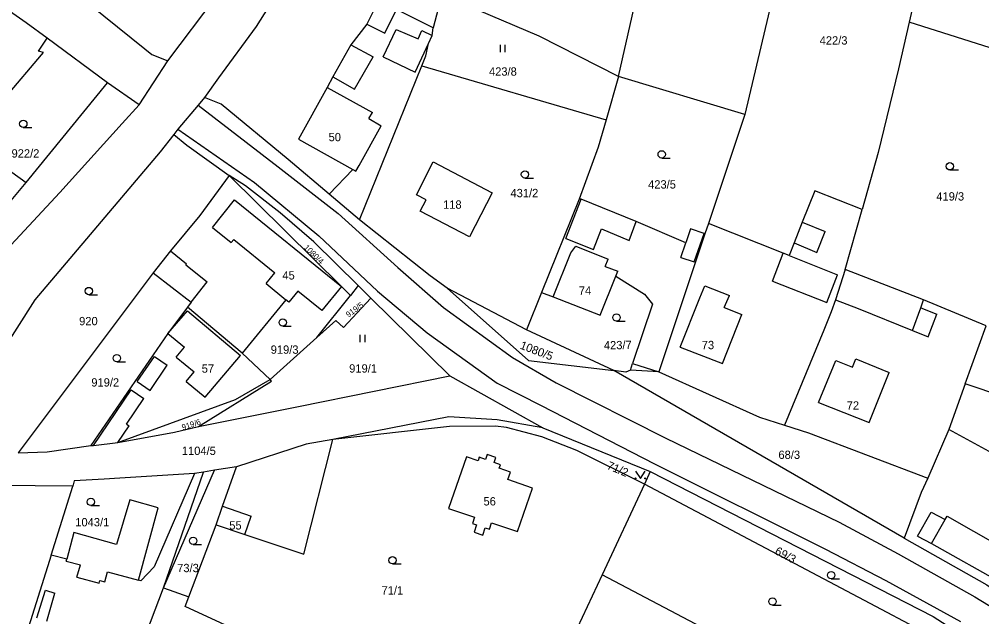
# Model space of a CAD drawing. Extents: x -746176 to -739709, y -1128407 to -1124482.
# Drawn here: x -742573.8 to -742377, y -1125982.8 to -1125860.6 of the extents above; entities that cross this region are included whole.
import ezdxf

# ---------------------------------------------------------------- set-up
doc = ezdxf.new("R2010")
doc.units = 0
for name, color, linetype in [('Hranice parcel', 7, 'Continuous'), ('Parcelní čísla', 7, 'Continuous'), ('Vnitřní kresba', 7, 'Continuous'), ('Značky kultur', 7, 'Continuous')]:
    doc.layers.add(name, color=color, linetype=linetype)

msp = doc.modelspace()

# ---------------------------------------------------------------- linework, layer by layer
at = {"layer": 'Hranice parcel'}
for p, q in [((-742411.59, -1125821.74), (-742425.41, -1125880.06)), ((-742386.83, -1125839.6), (-742391.8, -1125861.15)), ((-742487.36, -1125855.55), (-742489.14, -1125862.33)), ((-742361.26, -1125870.87), (-742391.8, -1125861.15)), ((-742555.75, -1125873.58), (-742568.08, -1125864.47)), ((-742549.27, -1125878.06), (-742543.37, -1125869.11)), ((-742504.18, -1125901.64), (-742491.48, -1125870.12)), ((-742491.48, -1125870.12), (-742453.8, -1125881.12)), ((-742451.26, -1125872.3), (-742453.8, -1125881.12)), ((-742425.41, -1125880.06), (-742451.26, -1125872.3)), ((-742572.38, -1125894), (-742555.75, -1125873.58)), ((-742549.27, -1125878.06), (-742555.75, -1125873.58)), ((-742425.41, -1125880.06), (-742432.86, -1125902.34)), ((-742583.94, -1125885.69), (-742572.38, -1125894)), ((-742530.83, -1125892.53), (-742507.9, -1125915.25)), ((-742577.49, -1125900.11), (-742572.38, -1125894)), ((-742504.18, -1125901.64), (-742510.39, -1125896.37)), ((-742459.32, -1125897.41), (-742466.99, -1125916.45)), ((-742404.91, -1125911.78), (-742401.44, -1125899.49)), ((-742432.86, -1125902.34), (-742433.58, -1125904.47)), ((-742433.58, -1125904.47), (-742443.02, -1125932.7)), ((-742546.38, -1125912.47), (-742573.99, -1125949.25)), ((-742506.08, -1125917.05), (-742507.9, -1125915.25)), ((-742504.5, -1125915.04), (-742506.08, -1125917.05)), ((-742470.08, -1125924.13), (-742486.25, -1125915.58)), ((-742466.99, -1125916.45), (-742470.08, -1125924.13)), ((-742512.91, -1125925.68), (-742506.08, -1125917.05)), ((-742501.86, -1125917.64), (-742485.76, -1125933.54)), ((-742528.19, -1125928.89), (-742539.35, -1125919.44)), ((-742452.23, -1125932.44), (-742470.08, -1125924.13)), ((-742380.33, -1125935.12), (-742376.04, -1125923.32)), ((-742522.47, -1125934.25), (-742512.91, -1125925.68)), ((-742522.47, -1125934.25), (-742528.19, -1125928.89)), ((-742485.76, -1125933.54), (-742466.73, -1125944.13)), ((-742392.86, -1125966.72), (-742452.23, -1125932.44)), ((-742380.33, -1125935.12), (-742383.73, -1125944.51)), ((-742354.55, -1125943.93), (-742380.33, -1125935.12)), ((-742466.73, -1125944.13), (-742444.75, -1125953.11)), ((-742383.73, -1125944.51), (-742387.99, -1125954.45)), ((-742360.59, -1125957.08), (-742383.73, -1125944.51)), ((-742544.26, -1125976.88), (-742536.12, -1125953.2)), ((-742536.12, -1125953.2), (-742537.98, -1125953.5)), ((-742444.75, -1125953.11), (-742445.94, -1125955.65)), ((-742445.94, -1125955.65), (-742454.6, -1125974.2)), ((-742562.86, -1125956.05), (-742581.95, -1125955.95)), ((-742567.25, -1125970.2), (-742562.86, -1125956.05)), ((-742539.1, -1125978.71), (-742533.51, -1125963.98)), ((-742567.25, -1125970.2), (-742573.08, -1125988.58)), ((-742454.6, -1125974.2), (-742470.09, -1126007.17)), ((-742544.26, -1125976.88), (-742539.1, -1125978.71))]:
    msp.add_line(p, q, dxfattribs=at)
for points in [[(-742451.26, -1125872.3), (-742423.93, -1125751.58), (-742396.6, -1125630.87)], [(-742469.87, -1125754.46), (-742479.12, -1125772.95), (-742512.08, -1125840.96), (-742525.31, -1125862.03), (-742533.06, -1125872.56), (-742535.93, -1125876.56)], [(-742543.37, -1125869.11), (-742533.49, -1125855.94), (-742526.37, -1125842.12)], [(-742568.08, -1125864.47), (-742572.39, -1125861.31), (-742586.54, -1125851.33), (-742591, -1125848.62), (-742591.99, -1125848.03)], [(-742567.01, -1125851.37), (-742556.52, -1125859.9), (-742548.11, -1125866.6), (-742546.65, -1125867.77), (-742543.37, -1125869.11)], [(-742489.14, -1125862.33), (-742496.61, -1125858.56), (-742500.28, -1125856.71), (-742502.73, -1125861.57), (-742505.97, -1125865.78), (-742509.67, -1125872.35), (-742510.8, -1125874.53), (-742516.67, -1125885.09), (-742505.56, -1125891.34), (-742510.39, -1125896.37)], [(-742451.26, -1125872.3), (-742467.46, -1125864.05), (-742487.36, -1125855.55)], [(-742391.8, -1125861.15), (-742394.01, -1125870.7), (-742398.15, -1125887.84), (-742401.44, -1125899.49)], [(-742491.48, -1125870.12), (-742490.64, -1125868.04), (-742490.08, -1125865.53), (-742489.36, -1125863.92), (-742489.14, -1125862.33)], [(-742583.94, -1125885.69), (-742576.4, -1125876.29), (-742569.23, -1125867.87), (-742568.85, -1125867.39), (-742569.85, -1125867.14), (-742568.08, -1125864.47)], [(-742535.93, -1125876.56), (-742537.22, -1125878.12), (-742541.33, -1125883.08), (-742542.15, -1125884.13)], [(-742510.39, -1125896.37), (-742518.81, -1125889.24), (-742532.53, -1125877.94), (-742535.93, -1125876.56)], [(-742622.9, -1125956.15), (-742614.33, -1125945.77), (-742586.39, -1125918.45), (-742565.5, -1125896.03), (-742552.77, -1125881.87), (-742549.27, -1125878.06)], [(-742453.8, -1125881.12), (-742455.42, -1125886.74), (-742459.32, -1125897.41)], [(-742542.15, -1125884.13), (-742544.97, -1125887.72), (-742570.58, -1125918), (-742581.73, -1125935.37), (-742588.9, -1125948.74)], [(-742542.15, -1125884.13), (-742539.55, -1125886.34), (-742530.83, -1125892.53)], [(-742489.14, -1125889.75), (-742477.05, -1125896.1), (-742481.69, -1125905.09), (-742491.81, -1125899.8), (-742490.57, -1125897.54), (-742492.53, -1125896.46), (-742489.14, -1125889.75)], [(-742530.83, -1125892.53), (-742536.83, -1125900.7), (-742542.88, -1125907.93), (-742546.38, -1125912.47)], [(-742504.5, -1125915.04), (-742513.55, -1125906.11), (-742520.44, -1125900.17), (-742527.49, -1125894.67), (-742530.83, -1125892.53)], [(-742401.44, -1125899.49), (-742411.12, -1125895.65), (-742413.66, -1125902.11), (-742415.31, -1125906.31), (-742416.34, -1125908.93), (-742417.54, -1125908.45), (-742432.86, -1125902.34)], [(-742433.58, -1125904.47), (-742433.71, -1125904.43), (-742436.54, -1125903.47), (-742437.49, -1125906.29), (-742447.62, -1125901.95), (-742458.86, -1125897.36), (-742459.32, -1125897.41)], [(-742486.25, -1125915.58), (-742489.77, -1125913.07), (-742504.18, -1125901.64)], [(-742546.38, -1125912.47), (-742538.61, -1125918.44), (-742539.35, -1125919.44)], [(-742404.91, -1125911.78), (-742406.86, -1125917.94), (-742407.78, -1125920.45), (-742409.26, -1125924.16), (-742417.31, -1125943.6)], [(-742376.04, -1125923.32), (-742388.87, -1125917.99), (-742404.91, -1125911.78)], [(-742466.99, -1125916.45), (-742464.6, -1125917.38), (-742455, -1125921.11), (-742451.78, -1125913.15), (-742445.93, -1125916.84), (-742444.31, -1125918.83), (-742448.37, -1125931), (-742443.02, -1125932.7)], [(-742507.9, -1125915.25), (-742511.91, -1125920.18), (-742516.83, -1125916.2), (-742518.65, -1125918.45), (-742519.27, -1125917.94), (-742528.19, -1125928.89)], [(-742501.86, -1125917.64), (-742502.85, -1125916.66), (-742504.5, -1125915.04)], [(-742486.25, -1125915.58), (-742469.64, -1125930.37), (-742452.23, -1125932.44)], [(-742512.91, -1125925.68), (-742509.05, -1125922.22), (-742507.49, -1125923.6), (-742501.86, -1125917.64)], [(-742539.35, -1125919.44), (-742543.4, -1125924.86), (-742559.16, -1125947.76)], [(-742537.1, -1125943.85), (-742516.7, -1125939.77), (-742485.76, -1125933.54)], [(-742443.02, -1125932.7), (-742448.82, -1125932.36), (-742449.74, -1125932.78), (-742452.23, -1125932.44)], [(-742443.02, -1125932.7), (-742422.4, -1125941.96), (-742417.31, -1125943.6)], [(-742553.65, -1125947.14), (-742529.57, -1125938.33), (-742522.47, -1125934.25)], [(-742537.1, -1125943.85), (-742522.23, -1125934.58), (-742522.47, -1125934.25)], [(-742466.73, -1125944.13), (-742476.04, -1125942.52), (-742485.91, -1125941.93), (-742509.68, -1125946.54)], [(-742553.65, -1125947.14), (-742542.05, -1125945.01), (-742537.1, -1125943.85)], [(-742445.94, -1125955.65), (-742459.75, -1125948.8), (-742466.89, -1125946.02), (-742474.13, -1125944.08), (-742476.37, -1125943.84), (-742485.83, -1125943.85), (-742509.68, -1125946.54)], [(-742417.31, -1125943.6), (-742412.38, -1125945.19), (-742387.99, -1125954.45)], [(-742573.99, -1125949.25), (-742568.11, -1125949.08), (-742559.16, -1125947.76)], [(-742559.16, -1125947.76), (-742558.57, -1125947.74), (-742553.65, -1125947.14)], [(-742533.51, -1125963.98), (-742527.67, -1125965.96), (-742515.61, -1125969.96), (-742509.68, -1125946.54)], [(-742509.68, -1125946.54), (-742515.14, -1125947.5), (-742529.35, -1125952.1)], [(-742480.68, -1125962.42), (-742481.12, -1125963.73), (-742480.27, -1125964.02), (-742480.78, -1125965.52), (-742479, -1125966.12), (-742478.49, -1125964.62), (-742477.64, -1125964.9), (-742477.2, -1125963.59), (-742471.89, -1125965.38), (-742468.82, -1125956.52), (-742473.86, -1125954.74), (-742473.34, -1125953.24), (-742475.63, -1125952.43), (-742475.36, -1125951.69), (-742476.67, -1125951.22), (-742476.32, -1125950.24), (-742478.09, -1125949.62), (-742478.44, -1125950.6), (-742479.71, -1125950.15), (-742479.97, -1125950.9), (-742482.31, -1125950.08), (-742485.99, -1125960.63), (-742480.68, -1125962.42)], [(-742537.98, -1125953.5), (-742546.21, -1125972.61), (-742548.93, -1125975.45), (-742549.4, -1125975.3), (-742545.39, -1125960.48), (-742551.14, -1125958.9), (-742553.87, -1125967.99), (-742562.62, -1125965.54), (-742564.09, -1125970.98), (-742567.25, -1125970.2)], [(-742537.98, -1125953.5), (-742553.22, -1125954.47), (-742556.43, -1125954.63), (-742562.53, -1125955), (-742562.86, -1125956.05)], [(-742529.35, -1125952.1), (-742533.86, -1125952.83), (-742536.12, -1125953.2)], [(-742533.51, -1125963.98), (-742532.24, -1125960.14), (-742529.35, -1125952.1)], [(-742444.75, -1125953.11), (-742386.93, -1125982.77), (-742380.97, -1125986.53)], [(-742382.69, -1125989.14), (-742398.6, -1125980.67), (-742445.94, -1125955.65)], [(-742387.99, -1125954.45), (-742389.36, -1125957.36), (-742392.86, -1125966.72)], [(-742392.86, -1125966.72), (-742375.94, -1125976.23), (-742374.7, -1125977.14), (-742365.43, -1125982.55)], [(-742399.65, -1126003.37), (-742408.8, -1125998.36), (-742454.6, -1125974.2)], [(-742550.22, -1125993.2), (-742548.63, -1125988.42), (-742544.26, -1125976.88)], [(-742525.42, -1125987.39), (-742539.86, -1125980.7), (-742539.1, -1125978.71)]]:
    msp.add_lwpolyline(points, dxfattribs=at)
at = {"layer": 'Vnitřní kresba'}
for p, q in [((-742499.06, -1125863.42), (-742496.61, -1125858.56)), ((-742502.73, -1125861.57), (-742499.06, -1125863.42)), ((-742499.35, -1125868.29), (-742496.68, -1125862.69)), ((-742496.68, -1125862.69), (-742492.2, -1125864.62)), ((-742492.2, -1125864.62), (-742491.45, -1125862.87)), ((-742491.45, -1125862.87), (-742489.36, -1125863.92)), ((-742505.97, -1125865.78), (-742501.44, -1125868.3)), ((-742492.84, -1125871.4), (-742490.08, -1125865.53)), ((-742505.24, -1125874.9), (-742501.44, -1125868.3)), ((-742499.35, -1125868.29), (-742492.84, -1125871.4)), ((-742509.67, -1125872.35), (-742505.24, -1125874.9)), ((-742510.8, -1125874.53), (-742501.54, -1125879.62)), ((-742537.22, -1125878.12), (-742520.87, -1125890.79)), ((-742502.29, -1125880.85), (-742501.54, -1125879.62)), ((-742502.29, -1125880.85), (-742499.81, -1125882.36)), ((-742504.3, -1125890.51), (-742499.81, -1125882.36)), ((-742541.33, -1125883.08), (-742525.71, -1125893.94)), ((-742520.87, -1125890.79), (-742508.59, -1125900.34)), ((-742504.95, -1125891.68), (-742504.3, -1125890.51)), ((-742505.56, -1125891.34), (-742504.95, -1125891.68)), ((-742525.71, -1125893.94), (-742512.5, -1125904.89)), ((-742534.26, -1125903.18), (-742529.78, -1125897.51)), ((-742529.78, -1125897.51), (-742507.9, -1125915.25)), ((-742462.03, -1125905.4), (-742458.86, -1125897.36)), ((-742508.59, -1125900.34), (-742496.39, -1125911.34)), ((-742449.09, -1125905.82), (-742447.62, -1125901.95)), ((-742413.66, -1125902.11), (-742408.97, -1125903.96)), ((-742534.26, -1125903.18), (-742530.45, -1125906.26)), ((-742456.37, -1125907.69), (-742454.71, -1125903.47)), ((-742454.71, -1125903.47), (-742449.09, -1125905.82)), ((-742435.76, -1125910.23), (-742433.71, -1125904.43)), ((-742410.72, -1125908.26), (-742408.97, -1125903.96)), ((-742530.45, -1125906.26), (-742529.92, -1125905.6)), ((-742529.92, -1125905.6), (-742521.49, -1125912.43)), ((-742512.5, -1125904.89), (-742500.56, -1125916.22)), ((-742462.03, -1125905.4), (-742456.37, -1125907.69)), ((-742438.5, -1125909.28), (-742437.49, -1125906.29)), ((-742415.31, -1125906.31), (-742410.72, -1125908.26)), ((-742542.88, -1125907.93), (-742539.57, -1125910.59)), ((-742464.6, -1125917.38), (-742461.01, -1125908.34)), ((-742461.01, -1125908.34), (-742459.99, -1125907.02)), ((-742459.99, -1125907.02), (-742453.33, -1125909.63)), ((-742419.77, -1125914.17), (-742417.54, -1125908.45)), ((-742539.74, -1125910.8), (-742539.57, -1125910.59)), ((-742453.97, -1125911.14), (-742453.33, -1125909.63)), ((-742438.5, -1125909.28), (-742435.76, -1125910.23)), ((-742416.34, -1125908.93), (-742406.43, -1125912.88)), ((-742539.74, -1125910.8), (-742535.33, -1125914.3)), ((-742523.28, -1125914.65), (-742521.49, -1125912.43)), ((-742496.39, -1125911.34), (-742487.01, -1125919.55)), ((-742453.97, -1125911.14), (-742451.37, -1125912.13)), ((-742451.78, -1125913.15), (-742451.37, -1125912.13)), ((-742538.61, -1125918.44), (-742535.33, -1125914.3)), ((-742419.77, -1125914.17), (-742408.63, -1125918.53)), ((-742408.63, -1125918.53), (-742406.43, -1125912.88)), ((-742523.28, -1125914.65), (-742519.27, -1125917.94)), ((-742500.56, -1125916.22), (-742490.34, -1125924.69)), ((-742434.59, -1125917.55), (-742433.61, -1125915.09)), ((-742433.61, -1125915.09), (-742428.57, -1125917.11)), ((-742438.62, -1125927.64), (-742434.59, -1125917.55)), ((-742429.64, -1125919.52), (-742428.57, -1125917.11)), ((-742406.86, -1125917.94), (-742402.22, -1125919.77)), ((-742389.45, -1125919.59), (-742388.87, -1125917.99)), ((-742543.4, -1125924.86), (-742539.39, -1125920.19)), ((-742539.39, -1125920.19), (-742528.55, -1125929.36)), ((-742487.01, -1125919.55), (-742472.93, -1125929.77)), ((-742429.64, -1125919.52), (-742426.02, -1125920.95)), ((-742402.22, -1125919.77), (-742391.15, -1125924.26)), ((-742391.15, -1125924.26), (-742389.45, -1125919.59)), ((-742389.45, -1125919.59), (-742386.16, -1125920.91)), ((-742430.01, -1125931), (-742426.02, -1125920.95)), ((-742387.95, -1125925.55), (-742386.16, -1125920.91)), ((-742391.15, -1125924.26), (-742387.95, -1125925.55)), ((-742543.4, -1125924.86), (-742540.01, -1125927.67)), ((-742490.34, -1125924.69), (-742476.09, -1125935.01)), ((-742541.69, -1125929.69), (-742540.01, -1125927.67)), ((-742438.62, -1125927.64), (-742430.01, -1125931)), ((-742549.68, -1125934.66), (-742546.11, -1125929.56)), ((-742546.11, -1125929.56), (-742543.54, -1125931.35)), ((-742541.69, -1125929.69), (-742538.01, -1125932.67)), ((-742535.78, -1125937.86), (-742528.55, -1125929.36)), ((-742472.93, -1125929.77), (-742464.02, -1125934.96)), ((-742403.4, -1125931.74), (-742402.73, -1125930.07)), ((-742402.73, -1125930.07), (-742395.9, -1125932.8)), ((-742547.03, -1125936.52), (-742543.54, -1125931.35)), ((-742448.82, -1125932.36), (-742448.37, -1125931)), ((-742410.34, -1125939), (-742406.83, -1125930.35)), ((-742406.83, -1125930.35), (-742403.4, -1125931.74)), ((-742539.64, -1125934.64), (-742538.01, -1125932.67)), ((-742399.99, -1125943.09), (-742395.9, -1125932.8)), ((-742549.68, -1125934.66), (-742547.03, -1125936.52)), ((-742539.64, -1125934.64), (-742535.78, -1125937.86)), ((-742476.09, -1125935.01), (-742467.07, -1125939.61)), ((-742464.02, -1125934.96), (-742441.6, -1125946.26)), ((-742558.57, -1125947.74), (-742550.88, -1125936.37)), ((-742551.86, -1125943.37), (-742548.32, -1125938.17)), ((-742550.88, -1125936.37), (-742548.32, -1125938.17)), ((-742467.07, -1125939.61), (-742443.89, -1125951.53)), ((-742410.34, -1125939), (-742399.99, -1125943.09)), ((-742553.65, -1125947.14), (-742551.32, -1125943.73)), ((-742551.86, -1125943.37), (-742551.32, -1125943.73)), ((-742441.6, -1125946.26), (-742406.15, -1125963.41)), ((-742443.89, -1125951.53), (-742408.92, -1125968.97)), ((-742544.26, -1125976.88), (-742533.86, -1125952.83)), ((-742532.24, -1125960.14), (-742526.35, -1125962.21)), ((-742390.09, -1125966.29), (-742387.32, -1125961.4)), ((-742387.32, -1125961.4), (-742384.45, -1125962.91)), ((-742527.67, -1125965.96), (-742526.35, -1125962.21)), ((-742406.15, -1125963.41), (-742394.08, -1125969.92)), ((-742387.23, -1125967.82), (-742384.45, -1125962.91)), ((-742384.45, -1125962.91), (-742384.05, -1125962.22)), ((-742384.05, -1125962.22), (-742373.29, -1125968.32)), ((-742390.09, -1125966.29), (-742387.23, -1125967.82)), ((-742408.92, -1125968.97), (-742396.61, -1125975.35)), ((-742387.23, -1125967.82), (-742366.83, -1125979.29)), ((-742564.2, -1125971.41), (-742564.09, -1125970.98)), ((-742564.2, -1125971.41), (-742561.24, -1125972.19)), ((-742394.08, -1125969.92), (-742378.39, -1125978.73)), ((-742562.02, -1125974.66), (-742561.24, -1125972.19)), ((-742562.02, -1125974.66), (-742557.45, -1125975.89)), ((-742557.45, -1125975.89), (-742557.3, -1125975.35)), ((-742557.3, -1125975.35), (-742556.28, -1125975.62)), ((-742556.28, -1125975.62), (-742555.76, -1125973.63)), ((-742555.76, -1125973.63), (-742549.4, -1125975.3)), ((-742396.61, -1125975.35), (-742381.3, -1125983.74)), ((-742570.16, -1125983.03), (-742568.42, -1125977.34)), ((-742568.42, -1125977.34), (-742566.48, -1125977.96)), ((-742568.14, -1125983.67), (-742566.48, -1125977.96)), ((-742378.39, -1125978.73), (-742362.72, -1125988.35))]:
    msp.add_line(p, q, dxfattribs=at)
at = {"layer": 'Značky kultur'}
for p, q in [((-742475.41, -1125867.31), (-742475.41, -1125865.81)), ((-742474.41, -1125867.31), (-742474.41, -1125865.81)), ((-742572.96, -1125882.73), (-742571.21, -1125882.73)), ((-742442.41, -1125888.96), (-742440.66, -1125888.96)), ((-742383.48, -1125891.41), (-742381.73, -1125891.41)), ((-742470.38, -1125893.06), (-742468.63, -1125893.06)), ((-742559.56, -1125916.92), (-742557.81, -1125916.92)), ((-742451.65, -1125922.32), (-742449.9, -1125922.32)), ((-742519.91, -1125923.36), (-742518.16, -1125923.36)), ((-742504.06, -1125926.6), (-742504.06, -1125925.1)), ((-742503.06, -1125926.6), (-742503.06, -1125925.1)), ((-742553.84, -1125930.64), (-742552.09, -1125930.64)), ((-742559.13, -1125960.05), (-742557.38, -1125960.05)), ((-742538.24, -1125968), (-742536.49, -1125968)), ((-742497.45, -1125971.99), (-742495.7, -1125971.99)), ((-742407.77, -1125975.03), (-742406.02, -1125975.03)), ((-742419.74, -1125980.43), (-742417.99, -1125980.43))]:
    msp.add_line(p, q, dxfattribs=at)
msp.add_lwpolyline([(-742447.78, -1125952.99), (-742446.78, -1125954.49), (-742445.78, -1125952.99)], dxfattribs=at)
for centre, radius in [((-742572.96, -1125881.98), 0.75), ((-742442.41, -1125888.21), 0.75), ((-742383.48, -1125890.66), 0.75), ((-742470.38, -1125892.31), 0.75), ((-742559.56, -1125916.17), 0.75), ((-742519.91, -1125922.61), 0.75), ((-742451.65, -1125921.57), 0.75), ((-742553.84, -1125929.89), 0.75), ((-742447.78, -1125954.49), 0.1), ((-742445.78, -1125954.49), 0.1), ((-742559.13, -1125959.3), 0.75), ((-742538.24, -1125967.25), 0.75), ((-742497.45, -1125971.24), 0.75), ((-742407.77, -1125974.28), 0.75), ((-742419.74, -1125979.68), 0.75)]:
    msp.add_circle(centre, radius, dxfattribs=at)

# ---------------------------------------------------------------- texts
at = {"layer": 'Parcelní čísla'}
for s, p in [('422/3', (-742410.11, -1125865.76)), ('423/8', (-742477.73, -1125872.12)), ('50', (-742510.53, -1125885.53)), ('922/2', (-742575.36, -1125888.87)), ('423/5', (-742445.19, -1125895.21)), ('431/2', (-742473.34, -1125896.98)), ('419/3', (-742386.26, -1125897.66)), ('118', (-742487.12, -1125899.34)), ('45', (-742519.98, -1125913.81)), ('74', (-742459.36, -1125916.92)), ('920', (-742561.54, -1125923.17)), ('73', (-742434.22, -1125928.06)), ('919/3', (-742522.37, -1125929)), ('57', (-742536.47, -1125932.87)), ('919/1', (-742506.32, -1125932.85)), ('919/2', (-742559.05, -1125935.71)), ('72', (-742404.58, -1125940.42)), ('1104/5', (-742540.54, -1125949.7)), ('68/3', (-742418.54, -1125950.51)), ('56', (-742478.85, -1125960.03)), ('1043/1', (-742562.33, -1125964.3)), ('55', (-742530.84, -1125964.95)), ('73/3', (-742541.49, -1125973.67)), ('71/1', (-742499.7, -1125978.24))]:
    msp.add_text(s, height=1.7, dxfattribs=at).set_placement(p)
for s, height, rotation, p in [('1080/4', 1.19, 316, (-742515.7, -1125907.39)), ('919/5', 1.19, 36, (-742506.47, -1125921.64)), ('423/7', 1.7, 1, (-742454.22, -1125928.13)), ('1080/5', 1.7, 339, (-742471.53, -1125927.91)), ('919/6', 1.19, 18, (-742540.34, -1125944.67)), ('71/2', 1.7, 337, (-742453.77, -1125952.49)), ('69/3', 1.7, 332, (-742419.43, -1125969.87))]:
    msp.add_text(s, height=height, rotation=rotation, dxfattribs=at).set_placement(p)

doc.saveas('drawing.dxf')
